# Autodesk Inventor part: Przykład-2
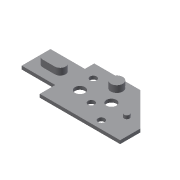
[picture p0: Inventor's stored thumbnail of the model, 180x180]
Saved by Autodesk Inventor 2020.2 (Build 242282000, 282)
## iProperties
Created: 2006-03
Part Number: Przykład-2
Document SubType Name: Modeling
Designer: F.Stasiak
Density: 1 g/cm^3
Material: Ogólny
Appearance: Domyślna
Manager: www.cadconsulting.pl
Company: Fabian Stasiak CAD Consulting
Author: F.Stasiak
Subject: Zbiór ćwiczeń. Autodesk Inventor 2020. Kurs podstawowy
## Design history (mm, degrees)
sketch "Szkic1"
  geometry: L1 (60, 0)-(-60, 0); L2 (-58.668, 80)-(10, 80); L3 (10, 80)-(60, 30); L4 (60, 30)-(60, 0); L5 (-58.668, 66)-(-110, 66); L6 (-110, 66)-(-110, 23); L7 (-110, 23)-(-60, 23); L8 (-60, 0)-(-60, 23); L9 (-58.668, 66)-(-58.668, 80); 2 further points
  constraints: 19 end point, 4 parallel, 4 perpendicular, 1 coincident, 1 horizontal, 1 midpoint
  dimensions: "d1" = 45 deg angle of L3 L1; "d5" = 50 horizontal distance of L3.end L2.end; "d46" = 43 distance of L5.end L6.end; "d47" = 23 distance of L1.end L7.end; "d48" = 80 distance between parallel lines of L2 L1; "d49" = 50 distance of L6.end L7.end
extrude "Wyciągnięcie proste1" new body sketch "Szkic1" distance "d6" = 5; taper "d7" = 0 deg
sketch "Szkic3"
  geometry: L1 (-58.668, 80)-(10, 80) reference; L2 (60, 0)-(-40, 0) reference; 4 further points
  constraints: 1 other
  dimensions: "d11" = 20 dimension on point (-40, 60); "d12" = 20 distance from line of point (-40, 60) L1; "d13" = 12 distance from line of L2 point (20, 12); "d14" = 80 dimension on point (20, 12); "d15" = 15 vertical distance of point (20, 12) point (-10, 27); "d16" = 30 horizontal distance of point (20, 12) point (-10, 27)
hole "Otwór1" sketch "Szkic3" at (20, 12), (-10, 27), (-40, 60) diameter "d17" = 10; stored, may be unused: countersink angle "d21" = 90 deg, drill point angle "d23" = 118 deg; dims "d18" = 6, "d19" = 4, "d20" = 2, "d22" = 8
sketch "Szkic4"
  geometry: C1 r 5 at (-40, 60) reference; C2 r 5 at (-10, 27) reference; 2 further points
  dimensions: "d24" = 25 vertical distance of C1.centre point (-35, 35); "d26" = 5 horizontal distance of C1.centre point (-35, 35); "d27" = 15 horizontal distance of C2.centre point (5, 42); "d28" = 15 horizontal distance of C2.centre point (5, 42)
hole "Otwór2" sketch "Szkic4" at (-35, 35), (5, 42) diameter "d29" = 15; stored, may be unused: countersink angle "d33" = 90 deg, drill point angle "d35" = 118 deg; dims "d30" = 6, "d31" = 4, "d32" = 2, "d34" = 8
sketch "Szkic5"
  geometry: L1 (-58.668, 80)-(10, 80) reference; C1 r 9 at (-10, 65); 1 further point
  constraints: 1 centre point, 1 other
  dimensions: "d36" = 18 diameter of C1; "d37" = 15 distance from line of L1 C1.centre; "d38" = 50 dimension on C1.centre
extrude "Wyciągnięcie proste3" join sketch "Szkic5" distance "d39" = 10; taper "d40" = 0 deg
sketch "Szkic6"
  geometry: L1 (60, 30)-(60, 0) reference; L2 (-58.668, 80)-(10, 80) reference; C1 r 4 at (35, 35)
  constraints: 1 centre point
  dimensions: "d41" = 8 diameter of C1; "d42" = 25 distance from line of L1 C1.centre; "d43" = 45 distance from line of L2 C1.centre
extrude "Wyciągnięcie proste4" join sketch "Szkic6" distance "d44" = 5; taper "d45" = 0 deg
sketch "Szkic7"
  geometry: L1 (-74, 36.5)-(-92, 36.5); L2 (-92, 52.5)-(-74, 52.5); L3 (-110, 23)-(-110, 66) reference; L4 (-110, 44.5)-(-92, 44.5); A1 r 8 centre (-92, 44.5) between (-92, 52.5) and (-92, 36.5); A2 r 8 centre (-74, 44.5) between (-74, 36.5) and (-74, 52.5)
  constraints: 6 end point, 4 point on circle, 4 tangent, 2 centre point, 2 horizontal, 1 midpoint, 1 parallel
  dimensions: "d50" = 8 radius of A2; "d51" = 18 distance of A2.centre L4.end; "d52" = 18 distance from line of L4.end L3
extrude "Wyciągnięcie proste5" join sketch "Szkic7" distance "d53" = 10; taper "d54" = 0 deg
node "Bryła1"
node "Korpusy bryłowe"
node "Korpusy powierzchniowe"
